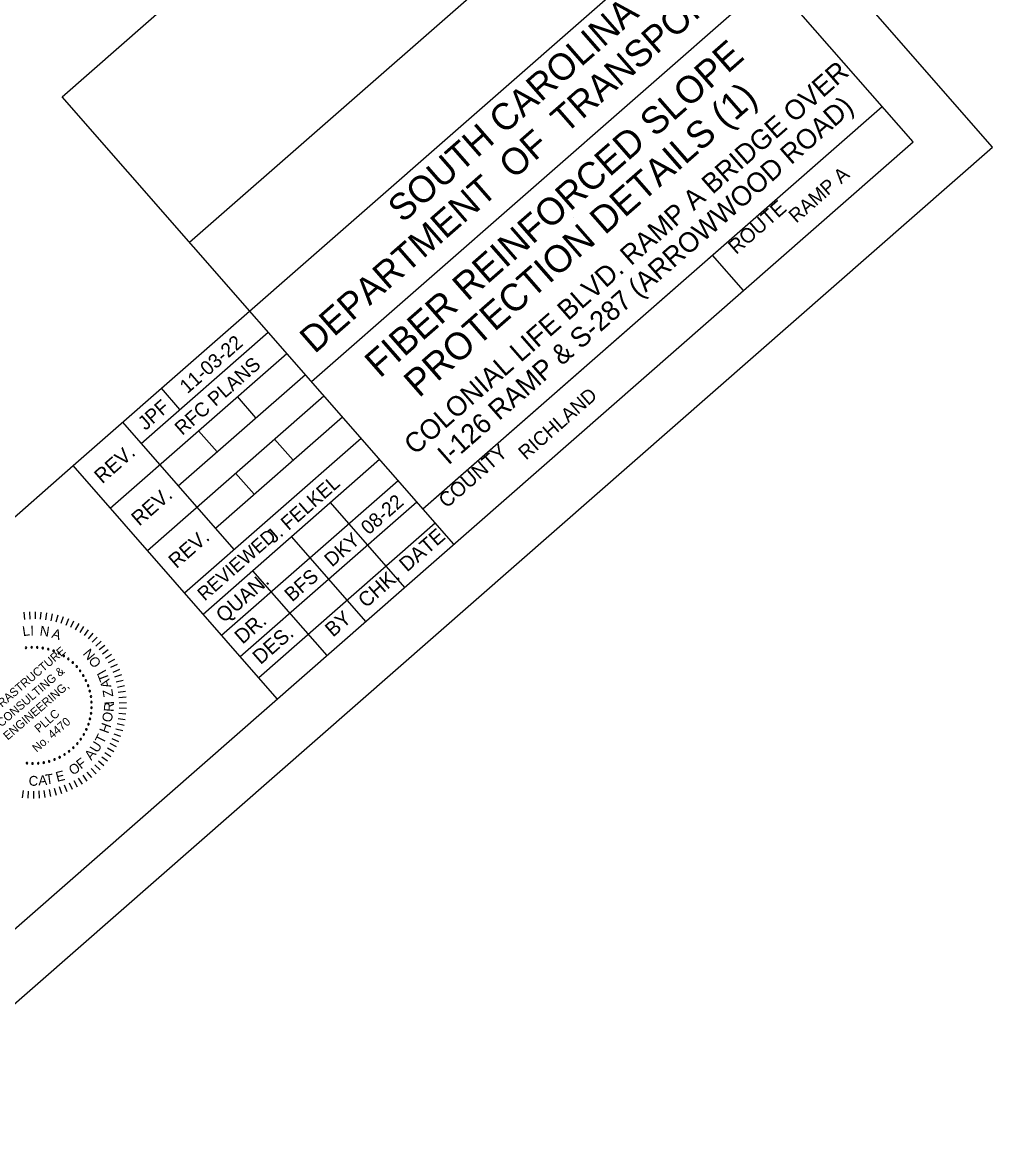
# Model space of a CAD drawing. Extents: x 1970965 to 1971298, y 796258 to 796581.
# Drawn here: x 1971228.7 to 1971297.6, y 796377.5 to 796457 of the extents above; entities that cross this region are included whole.
import ezdxf

# ---------------------------------------------------------------- set-up
doc = ezdxf.new("R2010")
doc.units = 0
for name, color, linetype in [('BR_BORDER LINES', 7, 'Continuous'), ('BR_TEXT', 7, 'Continuous'), ('Level 31', 7, 'Continuous')]:
    doc.layers.add(name, color=color, linetype=linetype)

msp = doc.modelspace()

# ---------------------------------------------------------------- linework, layer by layer
at = {"layer": 'BR_BORDER LINES'}
for p, q in [((1971291.955, 796448.534), (1971181.269, 796574.916)), ((1971231.543, 796451.738), (1971264.143, 796480.289)), ((1971240.583, 796441.419), (1971273.181, 796469.969)), ((1971232.321, 796425.552), (1971277.46, 796465.084)), ((1971249.252, 796431.518), (1971281.854, 796460.07)), ((1971259.355, 796419.982), (1971231.543, 796451.738)), ((1971257.159, 796422.49), (1971289.759, 796451.041)), ((1971257.746, 796423.004), (1971289.759, 796451.041)), ((1971089.346, 796271.087), (1971291.955, 796448.534)), ((1971279.918, 796437.992), (1971277.722, 796440.499)), ((1971237.15, 796427.122), (1971246.178, 796435.029)), ((1971234.957, 796422.543), (1971247.495, 796433.524)), ((1971239.785, 796424.113), (1971248.813, 796432.019)), ((1971249.252, 796431.518), (1971249.252, 796431.518)), ((1971239.908, 796429.538), (1971238.591, 796431.043)), ((1971237.592, 796419.533), (1971250.131, 796430.515)), ((1971245.302, 796428.945), (1971243.985, 796430.449)), ((1971242.421, 796421.104), (1971251.449, 796429.01)), ((1971235.832, 796428.627), (1971243.739, 796419.599)), ((1971240.228, 796416.524), (1971252.766, 796427.505)), ((1971242.544, 796426.529), (1971241.226, 796428.033)), ((1971247.938, 796425.935), (1971246.62, 796427.44)), ((1971241.546, 796415.02), (1971254.084, 796426.001)), ((1971200.032, 796397.273), (1971232.321, 796425.552)), ((1971246.817, 796409.001), (1971232.321, 796425.552)), ((1971245.179, 796423.519), (1971243.862, 796425.024)), ((1971242.863, 796413.515), (1971255.402, 796424.496)), ((1971244.181, 796412.01), (1971256.72, 796422.992)), ((1971250.573, 796422.926), (1971255.844, 796416.908)), ((1971245.499, 796410.506), (1971258.037, 796421.487)), ((1971247.815, 796420.51), (1971253.086, 796414.492)), ((1971245.056, 796418.094), (1971250.327, 796412.076))]:
    msp.add_line(p, q, dxfattribs=at)
at = {"layer": 'BR_TEXT'}
for p, q in [((1971228.824, 796415.146), (1971228.875, 796414.64)), ((1971229.227, 796415.174), (1971229.247, 796414.665)), ((1971229.631, 796415.178), (1971229.62, 796414.668)), ((1971230.034, 796415.156), (1971229.992, 796414.649)), ((1971230.435, 796415.111), (1971230.363, 796414.606)), ((1971230.833, 796415.04), (1971230.73, 796414.542)), ((1971231.226, 796414.946), (1971231.092, 796414.454)), ((1971231.612, 796414.828), (1971231.449, 796414.345)), ((1971231.99, 796414.687), (1971231.798, 796414.215)), ((1971232.359, 796414.522), (1971232.139, 796414.063)), ((1971232.718, 796414.336), (1971232.469, 796413.891)), ((1971233.064, 796414.128), (1971232.789, 796413.699)), ((1971233.397, 796413.899), (1971233.096, 796413.488)), ((1971233.715, 796413.651), (1971233.39, 796413.259)), ((1971234.018, 796413.383), (1971233.669, 796413.012)), ((1971234.303, 796413.098), (1971233.933, 796412.748)), ((1971234.571, 796412.796), (1971234.18, 796412.469)), ((1971234.82, 796412.478), (1971234.41, 796412.176)), ((1971235.049, 796412.145), (1971234.621, 796411.869)), ((1971235.258, 796411.799), (1971234.814, 796411.549)), ((1971235.445, 796411.441), (1971234.986, 796411.219)), ((1971235.609, 796411.072), (1971235.138, 796410.878)), ((1971235.751, 796410.694), (1971235.269, 796410.529)), ((1971235.87, 796410.308), (1971235.379, 796410.173)), ((1971235.965, 796409.916), (1971235.466, 796409.811)), ((1971236.035, 796409.518), (1971235.531, 796409.443)), ((1971236.082, 796409.117), (1971235.574, 796409.073)), ((1971236.101, 796408.31), (1971235.592, 796408.328)), ((1971236.103, 796408.713), (1971235.594, 796408.701)), ((1971236.021, 796407.506), (1971235.518, 796407.586)), ((1971236.073, 796407.907), (1971235.566, 796407.956)), ((1971235.845, 796406.718), (1971235.355, 796406.859)), ((1971235.945, 796407.11), (1971235.448, 796407.22)), ((1971235.574, 796405.958), (1971235.105, 796406.157)), ((1971235.721, 796406.334), (1971235.241, 796406.504)), ((1971234.999, 796404.893), (1971234.574, 796405.174)), ((1971235.212, 796405.236), (1971234.771, 796405.491)), ((1971235.404, 796405.591), (1971234.948, 796405.819)), ((1971234.24, 796403.951), (1971233.873, 796404.304)), ((1971234.512, 796404.249), (1971234.125, 796404.58)), ((1971234.765, 796404.564), (1971234.358, 796404.87)), ((1971233.322, 796403.162), (1971233.026, 796403.577)), ((1971233.644, 796403.406), (1971233.323, 796403.802)), ((1971233.95, 796403.669), (1971233.606, 796404.045)), ((1971231.524, 796402.258), (1971231.367, 796402.743)), ((1971231.905, 796402.394), (1971231.718, 796402.868)), ((1971232.276, 796402.553), (1971232.061, 796403.015)), ((1971232.637, 796402.735), (1971232.394, 796403.182)), ((1971232.986, 796402.938), (1971232.716, 796403.37)), ((1971228.732, 796401.979), (1971228.789, 796402.485)), ((1971229.135, 796401.945), (1971229.161, 796402.454)), ((1971229.539, 796401.936), (1971229.534, 796402.446)), ((1971229.942, 796401.952), (1971229.906, 796402.46)), ((1971230.344, 796401.992), (1971230.277, 796402.497)), ((1971230.743, 796402.057), (1971230.645, 796402.557)), ((1971231.137, 796402.146), (1971231.009, 796402.639))]:
    msp.add_line(p, q, dxfattribs=at)
for centre, start, end in [((1971228.975, 796412.625), 7.50808, 187.50808), ((1971228.975, 796412.625), 187.50808, 7.50808), ((1971229.373, 796412.657), 1.96962, 181.96962), ((1971229.373, 796412.657), 181.96962, 1.96962), ((1971229.771, 796412.65), 356.43116, 176.43116), ((1971229.771, 796412.65), 176.43116, 356.43116), ((1971230.167, 796412.606), 170.8927, 350.8927), ((1971230.167, 796412.606), 350.8927, 170.8927), ((1971230.557, 796412.523), 165.35424, 345.35424), ((1971230.557, 796412.523), 345.35424, 165.35424), ((1971230.938, 796412.403), 159.81578, 339.81578), ((1971230.938, 796412.403), 339.81578, 159.81578), ((1971231.304, 796412.247), 154.27732, 334.27732), ((1971231.304, 796412.247), 334.27732, 154.27732), ((1971231.654, 796412.056), 148.73885, 328.73885), ((1971231.654, 796412.056), 328.73885, 148.73885), ((1971231.984, 796411.832), 143.20039, 323.20039), ((1971231.984, 796411.832), 323.20039, 143.20039), ((1971232.291, 796411.577), 137.66193, 317.66193), ((1971232.291, 796411.577), 317.66193, 137.66193), ((1971232.572, 796411.294), 132.12347, 312.12347), ((1971232.572, 796411.294), 312.12347, 132.12347), ((1971232.824, 796410.986), 126.58501, 306.58501), ((1971232.824, 796410.986), 306.58501, 126.58501), ((1971233.045, 796410.654), 121.04655, 301.04655), ((1971233.045, 796410.654), 301.04655, 121.04655), ((1971233.233, 796410.303), 115.50808, 295.50808), ((1971233.233, 796410.303), 295.50808, 115.50808), ((1971233.387, 796409.935), 109.96962, 289.96962), ((1971233.387, 796409.935), 289.96962, 109.96962), ((1971233.504, 796409.554), 104.43116, 284.43116), ((1971233.504, 796409.554), 284.43116, 104.43116), ((1971233.584, 796409.163), 98.8927, 278.8927), ((1971233.584, 796409.163), 278.8927, 98.8927), ((1971233.625, 796408.767), 93.35424, 273.35424), ((1971233.629, 796408.368), 87.81578, 267.81578), ((1971233.625, 796408.767), 273.35424, 93.35424), ((1971233.629, 796408.368), 267.81578, 87.81578), ((1971233.52, 796407.579), 76.73885, 256.73885), ((1971233.52, 796407.579), 256.73885, 76.73885), ((1971233.593, 796407.971), 82.27732, 262.27732), ((1971233.593, 796407.971), 262.27732, 82.27732), ((1971233.262, 796406.826), 65.66193, 245.66193), ((1971233.262, 796406.826), 245.66193, 65.66193), ((1971233.409, 796407.196), 71.20039, 251.20039), ((1971233.409, 796407.196), 251.20039, 71.20039), ((1971232.617, 796405.823), 49.04655, 229.04655), ((1971232.864, 796406.136), 54.58501, 234.58501), ((1971232.864, 796406.136), 234.58501, 54.58501), ((1971233.08, 796406.471), 60.12347, 240.12347), ((1971233.08, 796406.471), 240.12347, 60.12347), ((1971231.712, 796405.047), 32.43116, 212.43116), ((1971231.712, 796405.047), 212.43116, 32.43116), ((1971232.038, 796405.276), 37.96962, 217.96962), ((1971232.038, 796405.276), 217.96962, 37.96962), ((1971232.341, 796405.535), 43.50808, 223.50808), ((1971232.341, 796405.535), 223.50808, 43.50808), ((1971232.617, 796405.823), 229.04655, 49.04655), ((1971229.043, 796404.434), 353.66193, 173.66193), ((1971229.043, 796404.434), 173.66193, 353.66193), ((1971229.441, 796404.408), 359.20039, 179.20039), ((1971229.441, 796404.408), 179.20039, 359.20039), ((1971229.839, 796404.421), 4.73885, 184.73885), ((1971229.839, 796404.421), 184.73885, 4.73885), ((1971230.234, 796404.472), 10.27732, 190.27732), ((1971230.234, 796404.472), 190.27732, 10.27732), ((1971230.623, 796404.562), 15.81578, 195.81578), ((1971230.623, 796404.562), 195.81578, 15.81578), ((1971231.001, 796404.688), 21.35424, 201.35424), ((1971231.001, 796404.688), 201.35424, 21.35424), ((1971231.365, 796404.85), 26.8927, 206.8927), ((1971231.365, 796404.85), 206.8927, 26.8927)]:
    msp.add_arc(centre, 0.0561, start, end, dxfattribs=at)
at = {"layer": 'Level 31'}
for p, q in [((1971297.603, 796448.164), (1971181.646, 796580.564)), ((1971080.947, 796258.416), (1971297.603, 796448.164)), ((1971267.874, 796443.145), (1971267.874, 796443.145))]:
    msp.add_line(p, q, dxfattribs=at)

# ---------------------------------------------------------------- texts
at = {"layer": 'BR_TEXT'}
for s, height, rotation, p in [('DEPARTMENT  OF  TRANSPORTATION', 1.88696, 41.21202, (1971249.466, 796433.449)), ('SOUTH CAROLINA', 1.88696, 41.21202, (1971255.722, 796442.732)), ('FIBER REINFORCED SLOPE', 1.92, 41.21202, (1971254.097, 796431.718)), ('COLONIAL LIFE BLVD. RAMP A BRIDGE OVER', 1.4, 41.21202, (1971256.586, 796426.259)), ('PROTECTION DETAILS (1)', 1.92, 41.21202, (1971256.874, 796430.321)), ('I-126 RAMP & S-287 (ARROWWOOD ROAD)', 1.4, 41.21202, (1971258.96, 796425.546)), ('RAMP A', 1, 41.21202, (1971283.664, 796442.721)), ('ROUTE', 1.04, 41.21202, (1971279.397, 796440.495)), ('11-03-22', 1, 41.21202, (1971240.433, 796430.613)), ('RFC PLANS', 1, 41.21202, (1971240.074, 796427.651)), ('RICHLAND', 1, 41.21202, (1971264.471, 796425.912)), ('JPF', 1, 41.21202, (1971237.459, 796428.009)), ('REV.', 1.04, 41.21202, (1971234.384, 796424.225)), ('COUNTY', 1.04, 41.21202, (1971258.834, 796422.486)), ('J. FELKEL', 1, 41.21202, (1971246.549, 796419.98)), ('REV.', 1.04, 41.21202, (1971237.019, 796421.216)), ('08-22', 1, 41.21202, (1971253.298, 796420.593)), ('DATE', 1.04, 41.21202, (1971256.034, 796417.962)), ('REV.', 1.04, 41.21202, (1971239.655, 796418.207)), ('REVIEWED', 0.96, 41.21202, (1971241.664, 796415.905)), ('DKY', 1, 41.21202, (1971250.698, 796418.316)), ('BFS', 1, 41.21202, (1971247.87, 796415.839)), ('CHK.', 1.04, 41.21202, (1971253.115, 796415.404)), ('QUAN.', 1.04, 41.21202, (1971243.022, 796414.347)), ('DR.', 1.04, 41.21202, (1971244.349, 796412.834)), ('BY', 1.04, 41.21202, (1971250.77, 796413.335)), ('L', 0.698, 8.32004, (1971228.772, 796413.441)), ('I', 0.698, 0.79002, (1971229.288, 796413.49)), ('N', 0.698, 351.75999, (1971229.921, 796413.505)), ('A', 0.698, 342.72997, (1971230.747, 796413.352)), ('DES.', 1.04, 41.21202, (1971245.627, 796411.387)), ('INFRASTRUCTURE', 0.59817, 40.73885, (1971226.297, 796407.523)), ('N', 0.698, 130.42051, (1971233.943, 796412.123)), ('O', 0.698, 124.42051, (1971234.358, 796411.514)), ('CONSULTING &', 0.59817, 40.73885, (1971227.223, 796406.967)), ('I', 0.698, 119.12128, (1971234.709, 796410.925)), ('T', 0.698, 110.60741, (1971234.91, 796410.384)), ('ENGINEERING,', 0.59817, 40.73885, (1971227.682, 796406.035)), ('A', 0.698, 104.60741, (1971235.043, 796409.858)), ('Z', 0.698, 98.60741, (1971235.182, 796409.168)), ('R', 0.698, 85.73885, (1971235.19, 796408.059)), ('I', 0.698, 93.5459, (1971235.238, 796408.604)), ('No. 4470', 0.5982, 40.73885, (1971229.737, 796405.171)), ('PLLC', 0.5982, 40.73885, (1971229.901, 796406.558)), ('O', 0.698, 79.73885, (1971235.046, 796407.295)), ('H', 0.698, 69.73885, (1971234.811, 796406.493)), ('U', 0.698, 57.73885, (1971234.046, 796405.121)), ('T', 0.698, 63.73885, (1971234.47, 796405.751)), ('A', 0.698, 51.73885, (1971233.613, 796404.597)), ('O', 0.698, 31.73885, (1971232.284, 796403.548)), ('F', 0.698, 37.73885, (1971232.882, 796403.975)), ('C', 0.698, 355.73885, (1971229.143, 796402.857)), ('A', 0.698, 1.73885, (1971229.868, 796402.869)), ('T', 0.698, 7.73885, (1971230.398, 796402.924)), ('E', 0.698, 13.73885, (1971231.183, 796403.103))]:
    msp.add_text(s, height=height, rotation=rotation, dxfattribs=at).set_placement(p)

doc.saveas('drawing.dxf')
